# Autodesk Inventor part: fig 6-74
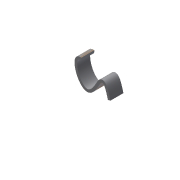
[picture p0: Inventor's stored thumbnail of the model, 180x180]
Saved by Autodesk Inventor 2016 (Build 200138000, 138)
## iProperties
Shininess: 64.0
Length Units: 11269
Angle Units: 11279
Time Units: 11290
Mass Units: 11283
Length Display Precision: 3
Angle Display Precision: 2
Compacted: True
Part Number: fig 6-74
Document SubType Name: Modeling
Created: 2002-12
Designer: deepak
Density: 1 g/cm^3
Material: Generic
Appearance: Default
Density: 0.0
Volumn: 0.0
Area: 0.0
PropertySet Name: Model Information
Control State: 0
Master: False
Checked Out: False
Author: deepak
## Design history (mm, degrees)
sketch "Sketch1"
  geometry: 5 further points
  constraints: 5 other
extrude_surface "ExtrusionSrf1" sketch "Sketch1" dims "d0" = 20, "d1" = 0
thicken "Thicken2" dims "d6" = 4, "d7" = 4
body "Solid1"
body "Srf1"
